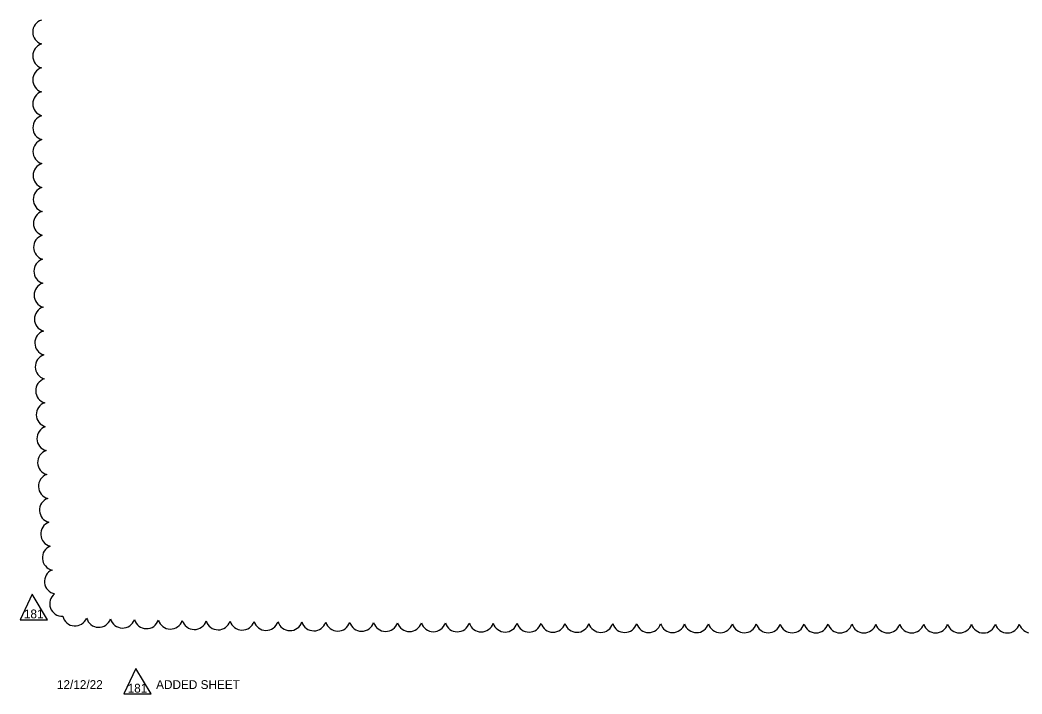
# Model space of a CAD drawing. Extents: x -811 to -790, y -2284 to -2178.
# Drawn here: x -811.08 to -803.16, y -2257.92 to -2252.59 of the extents above; entities that cross this region are included whole.
import ezdxf

# ---------------------------------------------------------------- set-up
doc = ezdxf.new("R2010")
doc.units = 0
doc.layers.add('ScratchEle_dp', color=7, linetype='Continuous')

msp = doc.modelspace()

# ---------------------------------------------------------------- linework, layer by layer
at = {"layer": 'ScratchEle_dp'}
for points in [[(-810.9836, -2257.1301), (-811.0784, -2257.3308), (-810.8622, -2257.3308)], [(-810.1638, -2257.7169), (-810.2586, -2257.9175), (-810.0424, -2257.9175)]]:
    msp.add_lwpolyline(points, close=True, dxfattribs=at)
for centre, start, end in [((-810.8794, -2252.6874), 107.52584, 252.52584), ((-810.8792, -2252.8764), 107.56719, 252.56719), ((-810.8789, -2253.0654), 107.61129, 252.61129), ((-810.8785, -2253.2544), 107.65843, 252.65843), ((-810.8779, -2253.4434), 107.709, 252.709), ((-810.8771, -2253.6323), 107.76343, 252.76343), ((-810.8761, -2253.8213), 107.82224, 252.82224), ((-810.875, -2254.0103), 107.88605, 252.88605), ((-810.8736, -2254.1992), 107.95561, 252.95561), ((-810.8719, -2254.3882), 108.03183, 253.03183), ((-810.87, -2254.5771), 108.11586, 253.11586), ((-810.8679, -2254.7661), 108.20912, 253.20912), ((-810.8653, -2254.955), 108.31345, 253.31345), ((-810.8625, -2255.1439), 108.43121, 253.43121), ((-810.8592, -2255.3328), 108.56556, 253.56556), ((-810.8554, -2255.5217), 108.72081, 253.72081), ((-810.8511, -2255.7105), 108.903, 253.903), ((-810.8461, -2255.8994), 109.12096, 254.12096), ((-810.8403, -2256.0881), 109.38818, 254.38818), ((-810.8335, -2256.2768), 109.72657, 254.72657), ((-810.8255, -2256.4654), 110.17469, 255.17469), ((-810.8156, -2256.6538), 110.80877, 255.80877), ((-810.8031, -2256.8419), 111.80931, 256.80931), ((-810.7858, -2257.029), 113.77584, 258.77584), ((-810.7447, -2257.2049), 127.48462, 272.48462), ((-810.644, -2257.2813), 193.17348, 338.17348), ((-810.4565, -2257.2918), 195.39639, 340.39639), ((-810.2679, -2257.2978), 195.97806, 340.97806), ((-810.0791, -2257.3023), 196.28744, 341.28744), ((-809.8902, -2257.306), 196.48754, 341.48754), ((-809.7013, -2257.3091), 196.63065, 341.63065), ((-809.5124, -2257.3118), 196.73959, 341.73959), ((-809.3235, -2257.3141), 196.8261, 341.8261), ((-809.1345, -2257.3162), 196.89697, 341.89697), ((-808.9455, -2257.3181), 196.95641, 341.95641), ((-808.7566, -2257.3198), 197.0072, 342.0072), ((-808.5676, -2257.3214), 197.05125, 342.05125), ((-808.3786, -2257.3228), 197.08993, 342.08993), ((-808.1897, -2257.3241), 197.12425, 342.12425), ((-808.0007, -2257.3253), 197.15498, 342.15498), ((-807.8117, -2257.3264), 197.18269, 342.18269), ((-807.6227, -2257.3274), 197.20786, 342.20786), ((-807.4337, -2257.3283), 197.23085, 342.23085), ((-807.2447, -2257.3292), 197.25195, 342.25195), ((-807.0557, -2257.3299), 197.27142, 342.27142), ((-806.8668, -2257.3307), 197.28945, 342.28945), ((-806.6778, -2257.3313), 197.30621, 342.30621), ((-806.4888, -2257.332), 197.32184, 342.32184), ((-806.2998, -2257.3325), 197.33647, 342.33647), ((-806.1108, -2257.333), 197.3502, 342.3502), ((-805.9218, -2257.3335), 197.36311, 342.36311), ((-805.7328, -2257.3339), 197.37529, 342.37529), ((-805.5438, -2257.3343), 197.3868, 342.3868), ((-805.3548, -2257.3347), 197.3977, 342.3977), ((-805.1658, -2257.335), 197.40804, 342.40804), ((-804.9768, -2257.3353), 197.41787, 342.41787), ((-804.7878, -2257.3355), 197.42723, 342.42723), ((-804.5988, -2257.3358), 197.43616, 342.43616), ((-804.4098, -2257.336), 197.44468, 342.44468), ((-804.2208, -2257.3361), 197.45283, 342.45283), ((-804.0318, -2257.3363), 197.46064, 342.46064), ((-803.8428, -2257.3364), 197.46812, 342.46812), ((-803.6538, -2257.3365), 197.4753, 342.4753), ((-803.4649, -2257.3366), 197.4822, 342.4822), ((-803.2759, -2257.3366), 197.48884, 342.48884), ((-803.0869, -2257.3366), 197.49523, 342.49523)]:
    msp.add_arc(centre, 0.0991, start, end, dxfattribs=at)

# ---------------------------------------------------------------- texts
for s, p in [('181', (-811.0481, -2257.3201)), ('12/12/22', (-810.7871, -2257.8783)), ('181', (-810.2282, -2257.9068)), ('ADDED SHEET', (-810.003, -2257.8783))]:
    msp.add_text(s, height=0.0696, dxfattribs=at).set_placement(p)

doc.saveas('drawing.dxf')
